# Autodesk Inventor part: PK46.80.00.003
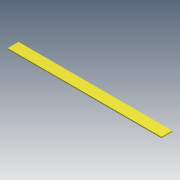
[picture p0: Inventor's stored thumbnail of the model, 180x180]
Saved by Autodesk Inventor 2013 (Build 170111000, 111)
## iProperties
Shininess: 64.0
Length Units: 11269
Angle Units: 11279
Time Units: 11290
Mass Units: 11283
Length Display Precision: 3
Angle Display Precision: 2
Compacted: True
Part Number: PK46.80.00.003
Document SubType Name: Modeling
Created: 2005-01
Material: Steel, Mild
Designer: SAlex
Manufacturer: Standard
Standards Organization: Custom
Density: 7.86 g/cm^3
Mass: 11161.2 g
Surface Area: 3144 cm^2
Volume: 1420 cm^3
Density: 0.0
Volumn: 0.0
Area: 0.0
PropertySet Name: Model Information
Control State: 0
Master: False
Checked Out: False
Checked Out Date: 2008-10-15
Last Check In Date: 2008-10-15
Author: SAlex
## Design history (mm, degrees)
sketch "Sketch1"
  geometry: L1 (0, 0)-(1420, 0); L2 (1420, 0)-(1420, 100); L3 (1420, 100)-(0, 100); L4 (0, 100)-(0, 0)
  constraints: 8 end point, 2 parallel, 1 horizontal, 1 perpendicular, 1 other
  dimensions: "d0" = 100 distance of L3.end L1.start; "d1" = 1420 distance of L2.end L3.end
extrude "Extrusion1" new body sketch "Sketch1" distance "d2" = 10; taper "d3" = 0 deg
body "Solid1"
